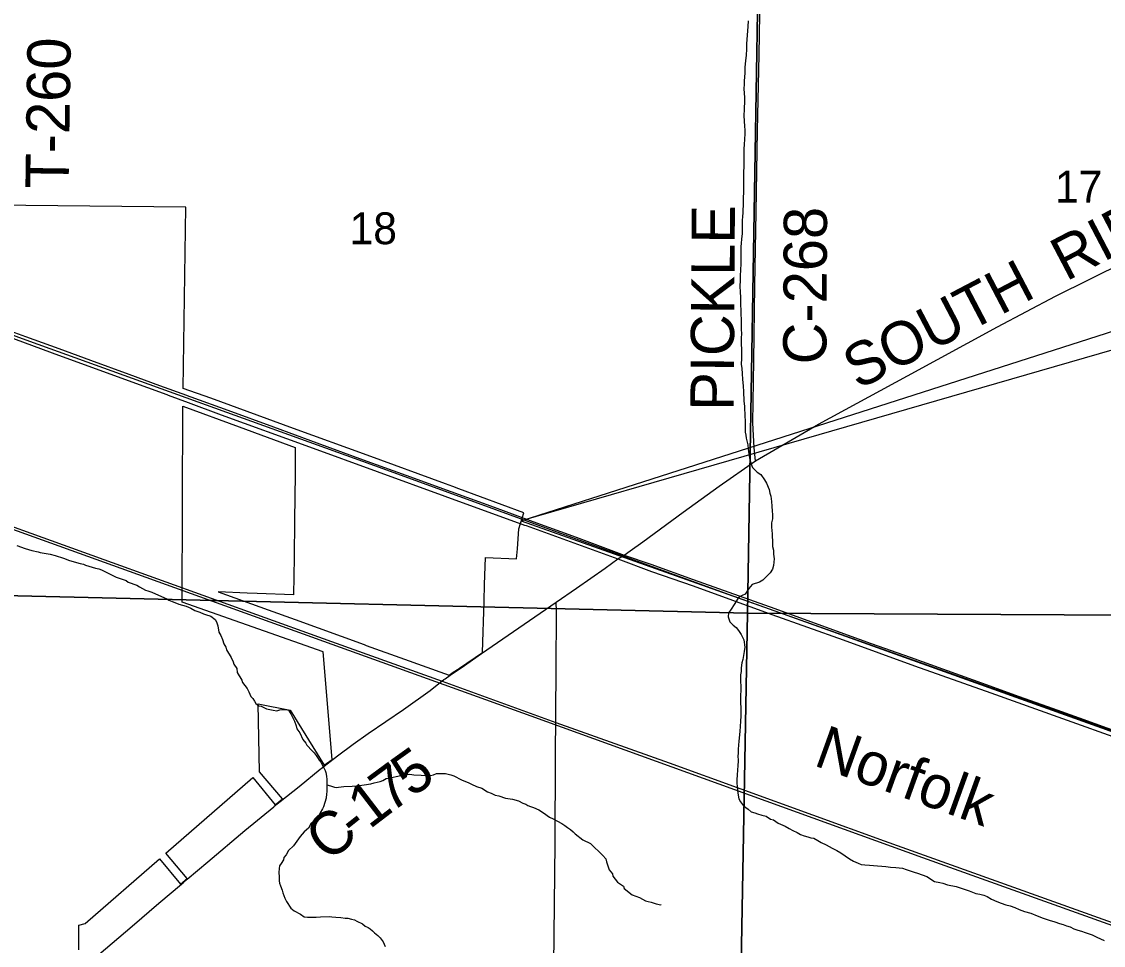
# Model space of a CAD drawing. Extents: x 0 to 34, y 0 to 22.
# Drawn here: x 3.229 to 4.651, y 16.762 to 17.976 of the extents above; entities that cross this region are included whole.
import ezdxf

# ---------------------------------------------------------------- set-up
doc = ezdxf.new("R2010")
doc.units = 0
for name, color, linetype in [('Default', 7, 'Continuous'), ('GM_X_County_Road', 7, 'Continuous'), ('GM_X_County_Road_Text', 7, 'Continuous'), ('GM_X_Minor_River', 7, 'Continuous'), ('GM_X_Rail_Line', 7, 'Continuous'), ('GM_X_Rail_Line_Text', 7, 'Continuous'), ('GM_X_Section', 7, 'Continuous'), ('GM_X_Section_Text', 7, 'Continuous'), ('GM_X_Township_Road', 7, 'Continuous'), ('GM_X_Township_Road_Text', 7, 'Continuous'), ('GM_X_US_Route', 7, 'Continuous'), ('SH_Text', 7, 'Continuous')]:
    doc.layers.add(name, color=color, linetype=linetype)

msp = doc.modelspace()

# ---------------------------------------------------------------- linework, layer by layer
at = {"layer": 'Default'}
for points in [[(3.3042, 16.7562), (3.3042, 16.7883), (3.3125, 16.7909), (3.41, 16.8758), (3.438, 16.8424), (3.4464, 16.8497), (3.4184, 16.8831), (3.5328, 16.9826), (3.5624, 16.9467), (3.572, 16.9545), (3.5414, 16.99), (3.5398, 17.0793), (3.5821, 17.0711), (3.6264, 16.9986), (3.6371, 17.0064), (3.6252, 17.1478), (3.4398, 17.2131), (3.4408, 17.4703), (3.5147, 17.4434), (3.5887, 17.4162), (3.5884, 17.3813), (3.5878, 17.3208), (3.5871, 17.2716), (3.5864, 17.2224), (3.5386, 17.2244), (3.5255, 17.2249), (3.4871, 17.2266), (3.5532, 17.2027), (3.5886, 17.19), (3.6793, 17.1571), (3.6816, 17.1562), (3.6878, 17.154), (3.726, 17.1403), (3.7908, 17.1171), (3.7962, 17.1208), (3.8017, 17.1244), (3.8045, 17.1262), (3.8346, 17.1467), (3.8367, 17.2142), (3.8374, 17.236), (3.8385, 17.2718), (3.8795, 17.2698), (3.8805, 17.2831), (3.8823, 17.3093), (3.8891, 17.3301), (3.8034, 17.3619), (3.7957, 17.3647), (3.786, 17.3682), (3.6831, 17.406), (3.5864, 17.4412), (3.4778, 17.4811), (3.4411, 17.4938), (3.4447, 17.732), (3.1921, 17.7348)], [(3.8857, 17.3198), (5.25, 16.8357), (6.6044, 16.3383), (8.5432, 15.6366)]]:
    msp.add_lwpolyline(points, dxfattribs=at)
at = {"layer": 'GM_X_County_Road'}
for p, q in [((3.6228, 16.9945), (3.6307, 17.0007)), ((3.5611, 16.9448), (3.5688, 16.951))]:
    msp.add_line(p, q, dxfattribs=at)
for points in [[(4.1934, 17.3987), (4.1919, 17.4159), (4.1902, 17.4485), (4.1913, 17.53), (4.1927, 17.6289), (4.1943, 17.7254), (4.1962, 17.8328), (4.1982, 17.9321), (4.2, 18.0395), (4.2016, 18.1352), (4.2026, 18.2066), (4.2034, 18.3191), (4.2042, 18.4555), (4.2041, 18.5613), (4.2014, 18.6463), (4.2003, 18.7008), (4.2014, 18.8419), (4.2016, 18.9531), (4.2014, 18.9854), (4.202, 19.0361)], [(4.0126, 17.27), (4.0211, 17.2749), (4.0289, 17.2804), (4.0453, 17.2923), (4.0983, 17.3311), (4.1458, 17.3655), (4.1934, 17.3987), (4.2763, 17.4468), (4.3934, 17.5102), (4.5116, 17.5747), (4.5879, 17.6151), (4.6791, 17.6602)], [(3.8336, 17.1453), (3.9315, 17.213), (3.9584, 17.2312), (3.996, 17.2575), (4.0126, 17.27)], [(3.7923, 17.117), (3.8067, 17.1268), (3.8336, 17.1453)], [(3.6307, 17.0007), (3.644, 17.0112), (3.6647, 17.0264), (3.6845, 17.0403), (3.731, 17.072), (3.7661, 17.097), (3.784, 17.1112)], [(3.784, 17.1112), (3.7856, 17.1124), (3.7923, 17.117)], [(3.5688, 16.951), (3.5936, 16.9708), (3.6213, 16.9933), (3.6228, 16.9945)], [(3.4466, 16.8488), (3.4736, 16.8717), (3.5224, 16.913), (3.5603, 16.9442), (3.5611, 16.9448)], [(3.4389, 16.8423), (3.4412, 16.8442), (3.4466, 16.8488)], [(3.2725, 16.7007), (3.2748, 16.7027), (3.3741, 16.7874), (3.4093, 16.8175), (3.4389, 16.8423)]]:
    msp.add_lwpolyline(points, dxfattribs=at)
at = {"layer": 'GM_X_Minor_River'}
for points in [[(4.1839, 17.9768), (4.1836, 17.9692), (4.1829, 17.9635), (4.1825, 17.9581), (4.1822, 17.9524), (4.1818, 17.9464), (4.1815, 17.9395), (4.1811, 17.9319), (4.1804, 17.9243), (4.1797, 17.916), (4.1793, 17.9087), (4.179, 17.903), (4.1786, 17.8981), (4.1787, 17.8928), (4.1783, 17.8882), (4.1787, 17.881), (4.1791, 17.8768), (4.1791, 17.8723), (4.1788, 17.8601), (4.1781, 17.8525), (4.1789, 17.8381), (4.1793, 17.8335), (4.1794, 17.8282), (4.1787, 17.8142), (4.1783, 17.8088), (4.178, 17.8001), (4.178, 17.7918), (4.1777, 17.7712), (4.1778, 17.7526), (4.1771, 17.7435), (4.1771, 17.7382), (4.1768, 17.7245), (4.1765, 17.7196), (4.1761, 17.7143), (4.1762, 17.6975), (4.1751, 17.6899), (4.1748, 17.6846), (4.1744, 17.6797), (4.1744, 17.674), (4.1741, 17.6671), (4.1741, 17.658), (4.1738, 17.6493), (4.1734, 17.6421), (4.1735, 17.6352), (4.1731, 17.6284), (4.1732, 17.6197), (4.1736, 17.6143), (4.1736, 17.6033), (4.1741, 17.5969), (4.1741, 17.5908), (4.1745, 17.5847), (4.1745, 17.5775), (4.1749, 17.5718)], [(4.1749, 17.5718), (4.175, 17.5657), (4.1746, 17.5604), (4.1747, 17.5505), (4.1751, 17.5467), (4.1751, 17.5331), (4.1748, 17.5255), (4.1756, 17.5198), (4.176, 17.5133), (4.1764, 17.5057), (4.1772, 17.497), (4.1776, 17.4894), (4.1784, 17.4773), (4.1789, 17.47), (4.1793, 17.4567), (4.1801, 17.4518), (4.1801, 17.4408), (4.1798, 17.4362), (4.1809, 17.4324), (4.1813, 17.4286), (4.1833, 17.4195), (4.1841, 17.4146), (4.1845, 17.4104), (4.186, 17.4002), (4.188, 17.3941), (4.1895, 17.3899), (4.1956, 17.3839), (4.2006, 17.3809), (4.2052, 17.3737), (4.2082, 17.3695), (4.2117, 17.3608), (4.2125, 17.3562), (4.2136, 17.3521), (4.2144, 17.3452), (4.2152, 17.3392), (4.2156, 17.3323), (4.216, 17.3282), (4.216, 17.3225), (4.2145, 17.3171), (4.2146, 17.3114), (4.215, 17.3073), (4.2154, 17.3027), (4.2158, 17.2902), (4.2158, 17.286), (4.217, 17.2811), (4.2174, 17.2761), (4.2182, 17.27), (4.2171, 17.2609), (4.216, 17.2564), (4.2126, 17.2514), (4.2077, 17.2461), (4.2032, 17.2419), (4.1986, 17.2392), (4.1891, 17.2361), (4.1846, 17.2308), (4.1801, 17.2235), (4.1759, 17.2216), (4.1714, 17.2189), (4.1665, 17.2113), (4.1608, 17.2025), (4.1582, 17.1987), (4.1575, 17.1938), (4.1598, 17.187), (4.164, 17.1828), (4.1682, 17.1798), (4.1712, 17.1756), (4.1747, 17.1703), (4.1781, 17.1635), (4.1793, 17.154), (4.1786, 17.1479), (4.1767, 17.1377), (4.1756, 17.1331), (4.1745, 17.1266), (4.1745, 17.1217), (4.1738, 17.1175), (4.1738, 17.1084), (4.1742, 17.1031), (4.1743, 17.0959), (4.1739, 17.0917), (4.1741, 17.0632), (4.1737, 17.0564), (4.1734, 17.0495), (4.173, 17.0434), (4.1716, 17.0298), (4.1712, 17.0256), (4.1709, 17.0195), (4.1709, 17.0146), (4.1705, 17.0104), (4.1706, 17.0051), (4.1702, 16.9971), (4.1698, 16.9933), (4.1695, 16.9846), (4.1692, 16.9807), (4.1692, 16.9751), (4.1696, 16.9709), (4.17, 16.9659), (4.1704, 16.9621), (4.1716, 16.9546), (4.1739, 16.9504), (4.1777, 16.9455), (4.1838, 16.9409)], [(3.2228, 17.2873), (3.2338, 17.2836), (3.2422, 17.2806), (3.2506, 17.2791), (3.2532, 17.2784), (3.2665, 17.2762), (3.273, 17.2743), (3.284, 17.2709), (3.292, 17.2675), (3.3057, 17.2638), (3.3102, 17.2627), (3.3129, 17.2616), (3.3262, 17.2578), (3.3304, 17.2567), (3.3338, 17.2556), (3.3365, 17.2541), (3.349, 17.2481), (3.3532, 17.2458), (3.3662, 17.2413), (3.3692, 17.2394), (3.3802, 17.2353), (3.384, 17.233), (3.392, 17.2285), (3.3947, 17.2278), (3.4, 17.2259), (3.405, 17.224), (3.4198, 17.2172), (3.4225, 17.2154), (3.4327, 17.2116), (3.4358, 17.2105), (3.4453, 17.2075), (3.4483, 17.2064), (3.4514, 17.2049), (3.4567, 17.2018), (3.4594, 17.2011), (3.4632, 17.1996), (3.4681, 17.1977), (3.4708, 17.1966), (3.4776, 17.1944), (3.4833, 17.1902), (3.4849, 17.1872), (3.4868, 17.1819), (3.4883, 17.1735), (3.491, 17.169), (3.4929, 17.164), (3.4949, 17.158), (3.4975, 17.1538), (3.4983, 17.1504), (3.5045, 17.1402), (3.5071, 17.1345), (3.5079, 17.1314), (3.5117, 17.1258), (3.5121, 17.1204), (3.5186, 17.1106), (3.5194, 17.1072), (3.5225, 17.1034), (3.5252, 17.0996), (3.5278, 17.0951), (3.5301, 17.089), (3.5328, 17.0864), (3.5351, 17.0829), (3.5366, 17.0799), (3.5408, 17.0769), (3.5439, 17.0762), (3.5507, 17.0728), (3.5595, 17.0709), (3.5644, 17.0702), (3.5682, 17.0713), (3.5765, 17.0717), (3.5796, 17.071), (3.583, 17.0661)], [(3.583, 17.0661), (3.5876, 17.0566), (3.5899, 17.0505), (3.5907, 17.0467), (3.5945, 17.0411), (3.5984, 17.0323), (3.6026, 17.0278), (3.6037, 17.0252), (3.611, 17.0176), (3.6136, 17.0149), (3.6163, 17.0115), (3.6178, 17.0089), (3.6201, 17.0055), (3.6224, 17.0028), (3.6255, 16.9968), (3.6278, 16.9918), (3.6286, 16.9892), (3.6297, 16.9843), (3.6301, 16.9801), (3.6302, 16.9637), (3.6295, 16.9611), (3.6291, 16.9554), (3.6258, 16.944), (3.6246, 16.9413), (3.6212, 16.936), (3.6179, 16.9284), (3.6122, 16.9242), (3.6092, 16.9215), (3.6062, 16.9158), (3.6005, 16.9112), (3.5952, 16.9051), (3.5862, 16.8929), (3.5797, 16.8868), (3.5767, 16.8807), (3.5737, 16.8773), (3.573, 16.8742), (3.57, 16.8696), (3.5681, 16.8666), (3.5673, 16.8628), (3.567, 16.8575), (3.5674, 16.8522), (3.5674, 16.8468), (3.5678, 16.8438), (3.569, 16.84), (3.5713, 16.8343), (3.5724, 16.8309), (3.5751, 16.8241), (3.577, 16.8195), (3.5828, 16.8108), (3.5873, 16.8074), (3.5953, 16.8029), (3.6003, 16.7995), (3.6049, 16.7988), (3.6159, 16.7992), (3.6216, 16.7996), (3.6337, 16.7997), (3.6367, 16.7993), (3.6421, 16.7989), (3.6485, 16.7986), (3.6542, 16.7979), (3.6576, 16.7975), (3.6626, 16.7964), (3.6664, 16.7953), (3.6694, 16.7938), (3.677, 16.7904), (3.6804, 16.7874), (3.6843, 16.7855), (3.6869, 16.7836), (3.6903, 16.7809), (3.6926, 16.7783), (3.6972, 16.7749), (3.7003, 16.7719), (3.7041, 16.7666), (3.7056, 16.7635), (3.7068, 16.7605)], [(3.6302, 16.9759), (3.6302, 16.9729), (3.6351, 16.9717), (3.6401, 16.9699), (3.6427, 16.9695), (3.6454, 16.9699), (3.6526, 16.9707), (3.6632, 16.9711), (3.67, 16.9715), (3.6791, 16.9727), (3.6879, 16.9743), (3.6924, 16.9754), (3.7004, 16.9774), (3.7038, 16.9785), (3.7083, 16.9812), (3.7152, 16.9824), (3.7235, 16.9843), (3.733, 16.9866), (3.739, 16.9867), (3.7444, 16.9859), (3.7539, 16.9856), (3.7607, 16.9853), (3.7664, 16.9853), (3.7702, 16.9861), (3.7743, 16.9876), (3.78, 16.988), (3.7861, 16.9877), (3.793, 16.9862), (3.7971, 16.9847), (3.807, 16.9794), (3.8169, 16.9757), (3.8203, 16.9738), (3.8268, 16.9708), (3.8337, 16.9685), (3.8413, 16.9636), (3.8462, 16.9621), (3.8512, 16.9591), (3.8561, 16.9584), (3.8648, 16.9554), (3.874, 16.9539), (3.8819, 16.9517), (3.8877, 16.949), (3.8915, 16.9475), (3.8945, 16.9456), (3.8979, 16.9445), (3.9017, 16.943), (3.9086, 16.94), (3.9151, 16.9362), (3.9227, 16.9306), (3.9276, 16.9283), (3.939, 16.9223), (3.9428, 16.9193), (3.9463, 16.917), (3.9505, 16.914), (3.9539, 16.911), (3.9566, 16.9087), (3.9665, 16.9008), (3.9767, 16.8959), (3.9928, 16.88), (3.997, 16.8755), (3.9977, 16.8717), (4.0012, 16.8614), (4.0054, 16.8561), (4.0062, 16.8531), (4.0123, 16.8452), (4.0199, 16.8399), (4.0211, 16.8365), (4.0314, 16.8282), (4.0409, 16.8248), (4.0489, 16.8206), (4.0523, 16.8195), (4.0565, 16.8188), (4.0629, 16.8165), (4.069, 16.815), (4.0694, 16.8149)], [(4.1838, 16.9409), (4.188, 16.9375), (4.1925, 16.936), (4.1963, 16.9349), (4.2017, 16.933), (4.2074, 16.9316), (4.2131, 16.9278), (4.2173, 16.9267), (4.2233, 16.9225), (4.2325, 16.9188), (4.2378, 16.9154), (4.2428, 16.9127), (4.2485, 16.9101), (4.2527, 16.9075), (4.2576, 16.906), (4.2622, 16.9045), (4.2663, 16.9033), (4.2701, 16.9026), (4.2755, 16.8996), (4.28, 16.8973), (4.2865, 16.8939), (4.2941, 16.8898), (4.3006, 16.8864), (4.3059, 16.8834), (4.3112, 16.8796), (4.317, 16.8755), (4.3223, 16.8728), (4.3284, 16.8698), (4.3322, 16.8683), (4.3371, 16.8676), (4.3432, 16.8672), (4.3538, 16.8665), (4.3595, 16.8662), (4.3648, 16.8654), (4.3709, 16.8647), (4.3781, 16.8644), (4.3869, 16.8633), (4.3914, 16.8618), (4.4021, 16.858), (4.4066, 16.8569), (4.4188, 16.8524), (4.4287, 16.846), (4.4359, 16.8445), (4.4397, 16.8438), (4.4458, 16.8415), (4.4572, 16.8393), (4.4743, 16.8337), (4.4831, 16.8303), (4.4884, 16.8292), (4.4937, 16.8277), (4.4979, 16.8262), (4.5036, 16.8228), (4.5108, 16.8198), (4.5165, 16.8176), (4.5226, 16.8153), (4.5283, 16.8138), (4.5344, 16.8116), (4.5401, 16.8089), (4.5473, 16.8063), (4.5553, 16.8041), (4.5637, 16.8007), (4.5717, 16.7977), (4.5797, 16.7951), (4.5869, 16.7928), (4.593, 16.7909), (4.5979, 16.7895), (4.6025, 16.7876), (4.607, 16.7865), (4.612, 16.7838), (4.6173, 16.7819), (4.6219, 16.7804), (4.6268, 16.779), (4.6321, 16.7771), (4.6359, 16.7756), (4.642, 16.7729), (4.6519, 16.7684)]]:
    msp.add_lwpolyline(points, dxfattribs=at)
at = {"layer": 'GM_X_Rail_Line'}
for points in [[(2.3438, 17.8832), (3.2394, 17.556), (3.7037, 17.3885), (4.1527, 17.2251), (5.0251, 16.9129), (5.72, 16.6602), (6.7111, 16.2981), (7.2308, 16.1113), (7.9999, 15.8344), (8.5456, 15.6361), (8.9, 15.5035)], [(2.1205, 17.682), (2.6475, 17.5103), (3.1194, 17.3438), (3.8981, 17.0634), (4.4129, 16.8774), (5.5123, 16.484), (6.2938, 16.2008), (7.1773, 15.8785), (7.9469, 15.6046), (8.6994, 15.3378), (8.9, 15.264)], [(3.1179, 17.348), (3.3371, 17.269), (3.6191, 17.1675), (3.7816, 17.1091), (3.9313, 17.055), (4.0801, 17.0018), (4.3626, 16.8993), (4.9898, 16.6747)]]:
    msp.add_lwpolyline(points, dxfattribs=at)
at = {"layer": 'GM_X_Section'}
for points in [[(4.1997, 18.1993), (4.1831, 17.1984), (3.1868, 17.2222), (3.2, 18.2405)], [(4.1997, 18.1993), (5.2018, 18.1949), (5.1818, 17.1932), (4.1831, 17.1984)], [(3.1868, 17.2222), (4.1831, 17.1984), (4.1651, 16.2036), (3.1722, 16.2262)], [(4.1831, 17.1984), (5.1818, 17.1932), (5.166, 16.1912), (4.1651, 16.2036)]]:
    msp.add_lwpolyline(points, close=True, dxfattribs=at)
at = {"layer": 'GM_X_Township_Road'}
msp.add_lwpolyline([(3.8988, 15.1968), (3.9249, 16.5318), (3.9284, 16.7361), (3.9302, 16.8958), (3.9305, 17.0084), (3.9315, 17.1247), (3.9321, 17.2011), (3.9315, 17.213)], dxfattribs=at)
at = {"layer": 'GM_X_US_Route'}
for points in [[(2.4837, 17.8296), (2.4907, 17.8257), (2.5468, 17.8044), (2.597, 17.7861), (2.6474, 17.7678), (2.6966, 17.7498), (2.7465, 17.7317), (2.7826, 17.7187), (2.8183, 17.7055), (2.8971, 17.6767), (2.9684, 17.6505), (3.0618, 17.6163), (3.1469, 17.5853), (3.1898, 17.5699), (3.1942, 17.5683), (3.2693, 17.5404), (3.3689, 17.5042), (3.4197, 17.4856)], [(3.1952, 17.5762), (3.2341, 17.5622), (3.2778, 17.5462), (3.3196, 17.5309), (3.3697, 17.5125), (3.4101, 17.4978), (3.4458, 17.4849)], [(3.4197, 17.4856), (3.4215, 17.485), (3.448, 17.4752)], [(3.4458, 17.4849), (3.4486, 17.4838), (3.4514, 17.4828)], [(3.448, 17.4752), (3.4914, 17.4593), (3.6072, 17.4172), (3.7853, 17.3523), (3.8901, 17.3142)], [(3.4514, 17.4828), (3.4998, 17.4652), (3.5598, 17.4433), (3.6168, 17.4222), (3.678, 17.4001), (3.7339, 17.3797), (3.7932, 17.3582), (3.8499, 17.3376), (3.9007, 17.319), (3.9579, 17.2982), (4.0211, 17.2749)], [(3.8901, 17.3142), (3.892, 17.3135), (4.0126, 17.27), (4.057, 17.2534), (4.1114, 17.2344), (4.2149, 17.1968), (4.3089, 17.1633), (4.4026, 17.1294), (4.5029, 17.0938), (4.597, 17.0599), (4.6755, 17.032)], [(4.0211, 17.2749), (4.0558, 17.263), (4.1118, 17.2429), (4.2189, 17.2045), (4.3093, 17.1718), (4.3457, 17.1586), (4.3966, 17.1407), (4.4395, 17.1252), (4.4966, 17.1048), (4.5402, 17.0891), (4.5833, 17.0737), (4.619, 17.0609), (4.676, 17.0405)]]:
    msp.add_lwpolyline(points, dxfattribs=at)
at = {"layer": 'SH_Text'}
msp.add_lwpolyline([(3.8857, 17.3198), (9.3048, 19.0572), (9.3048, 18.8857)], close=True, dxfattribs=at)

# ---------------------------------------------------------------- texts
at = {"layer": 'GM_X_County_Road_Text'}
for s, height, rotation, p in [('RIDGE', 0.05682, 27.6279, (4.6017, 17.6339)), ('PICKLE', 0.05682, 89.607, (4.1647, 17.4643)), ('C-268', 0.05682, 89.7247, (4.2866, 17.5253)), ('SOUTH', 0.05682, 27.6722, (4.3284, 17.4914)), ('5', 0.0568, 35.6042, (3.7415, 16.9553)), ('7', 0.0568, 36.3828, (3.7135, 16.9347)), ('1', 0.0568, 37.5183, (3.686, 16.9136)), ('C', 0.0568, 38.974, (3.6318, 16.8699)), ('-', 0.0568, 38.4562, (3.6679, 16.8992))]:
    msp.add_text(s, height=height, rotation=rotation, dxfattribs=at).set_placement(p)
at = {"layer": 'GM_X_Rail_Line_Text'}
msp.add_text('Norfolk', height=0.05663, rotation=340.1827, dxfattribs=at).set_placement((4.2683, 16.999))
at = {"layer": 'GM_X_Section_Text'}
for s, p in [('17', (4.5871, 17.738)), ('18', (3.66, 17.6833))]:
    msp.add_text(s, height=0.04186, rotation=0, dxfattribs=at).set_placement(p)
at = {"layer": 'GM_X_Township_Road_Text'}
msp.add_text('T-260', height=0.05682, rotation=89.1569, dxfattribs=at).set_placement((3.2907, 17.756))

doc.saveas('drawing.dxf')
